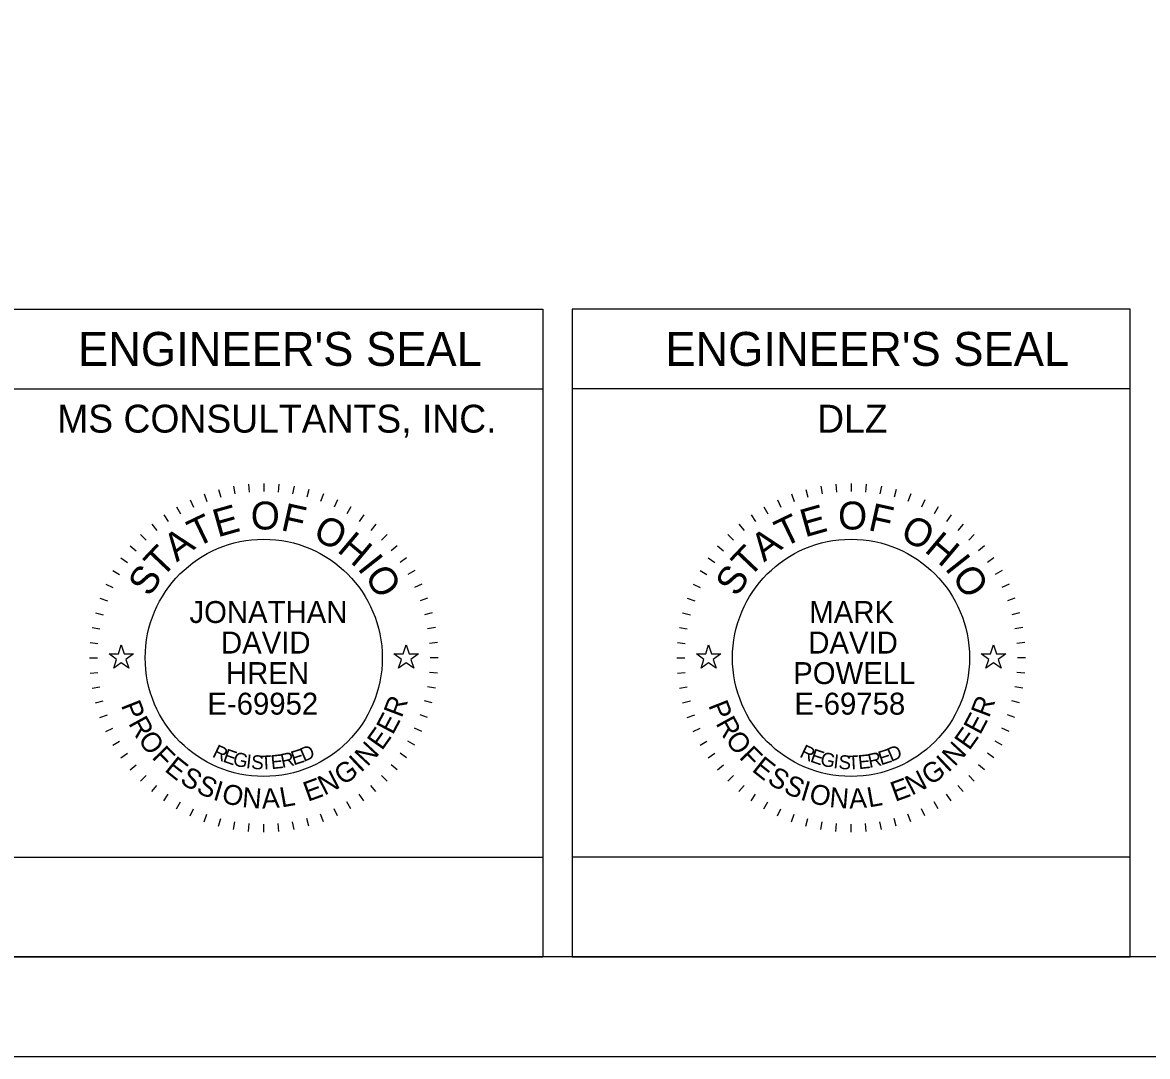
# Model space of a CAD drawing. Extents: x 0 to 34, y -1.2 to 22.
# Drawn here: x 25.22 to 30.87, y 0 to 5.19 of the extents above; entities that cross this region are included whole.
import ezdxf

# ---------------------------------------------------------------- set-up
doc = ezdxf.new("R2010")
doc.units = 0
for name, color, linetype in [('Default', 7, 'Continuous'), ('SH_Border', 7, 'Continuous'), ('SH_Cut_Line', 7, 'Continuous'), ('SH_Data', 7, 'Continuous')]:
    doc.layers.add(name, color=color, linetype=linetype)

msp = doc.modelspace()

# ---------------------------------------------------------------- linework, layer by layer
at = {"layer": 'Default'}
for points in [[(25.6575, 2.02), (25.7044, 2.02), (25.7189, 2.0645), (25.7334, 2.02), (25.7802, 2.02), (25.7423, 1.9924), (25.7568, 1.9478), (25.7189, 1.9754), (25.6809, 1.9478), (25.6954, 1.9924)], [(27.0875, 2.02), (27.1344, 2.02), (27.1489, 2.0645), (27.1634, 2.02), (27.2102, 2.02), (27.1723, 1.9924), (27.1868, 1.9478), (27.1489, 1.9754), (27.1109, 1.9478), (27.1254, 1.9924)], [(28.605, 2.02), (28.6519, 2.02), (28.6664, 2.0645), (28.6809, 2.02), (28.7278, 2.02), (28.6899, 1.9924), (28.7044, 1.9478), (28.6664, 1.9754), (28.6284, 1.9478), (28.6429, 1.9924)], [(30.035, 2.02), (30.0819, 2.02), (30.0964, 2.0645), (30.1109, 2.02), (30.1578, 2.02), (30.1199, 1.9924), (30.1344, 1.9478), (30.0964, 1.9754), (30.0584, 1.9478), (30.0729, 1.9924)]]:
    msp.add_lwpolyline(points, close=True, dxfattribs=at)
at = {"layer": 'SH_Border'}
msp.add_lwpolyline([(1.5, 21.5), (33.5, 21.5), (33.5, 0.5), (1.5, 0.5)], close=True, dxfattribs=at)
at = {"layer": 'SH_Cut_Line'}
msp.add_lwpolyline([(0, 0), (34, 0), (34, 22), (0, 22)], close=True, dxfattribs=at)
at = {"layer": 'SH_Data'}
for p, q in [((25.0339, 3.75), (27.8339, 3.75)), ((27.8339, 3.75), (27.8339, 0.5)), ((30.7814, 3.75), (27.9814, 3.75)), ((27.9814, 3.75), (27.9814, 0.5)), ((30.7814, 0.5), (30.7814, 3.75)), ((25.0339, 3.35), (27.8339, 3.35)), ((30.7814, 3.35), (27.9814, 3.35)), ((26.2074, 2.8452), (26.2178, 2.8065)), ((26.2819, 2.8617), (26.2889, 2.8223)), ((26.3576, 2.8717), (26.3611, 2.8318)), ((26.4339, 2.875), (26.4339, 2.835)), ((26.5101, 2.8717), (26.5066, 2.8318)), ((26.5858, 2.8617), (26.5789, 2.8223)), ((26.6603, 2.8452), (26.65, 2.8065)), ((29.155, 2.8452), (29.1653, 2.8065)), ((29.2295, 2.8617), (29.2364, 2.8223)), ((29.3052, 2.8717), (29.3086, 2.8318)), ((29.3814, 2.875), (29.3814, 2.835)), ((29.4577, 2.8717), (29.4542, 2.8318)), ((29.5334, 2.8617), (29.5264, 2.8223)), ((29.6079, 2.8452), (29.5975, 2.8065)), ((26.0641, 2.793), (26.081, 2.7568)), ((26.1346, 2.8222), (26.1483, 2.7846)), ((26.7331, 2.8222), (26.7195, 2.7846)), ((26.8037, 2.793), (26.7868, 2.7568)), ((29.0116, 2.793), (29.0285, 2.7568)), ((29.0822, 2.8222), (29.0958, 2.7846)), ((29.6807, 2.8222), (29.667, 2.7846)), ((29.7512, 2.793), (29.7343, 2.7568)), ((25.932, 2.7168), (25.9549, 2.684)), ((25.9964, 2.7578), (26.0164, 2.7231)), ((26.8714, 2.7578), (26.8514, 2.7231)), ((26.9357, 2.7168), (26.9128, 2.684)), ((28.8795, 2.7168), (28.9025, 2.684)), ((28.9439, 2.7578), (28.9639, 2.7231)), ((29.8189, 2.7578), (29.7989, 2.7231)), ((29.8833, 2.7168), (29.8604, 2.684)), ((25.8714, 2.6703), (25.8971, 2.6396)), ((26.9963, 2.6703), (26.9706, 2.6396)), ((28.819, 2.6703), (28.8447, 2.6396)), ((29.9439, 2.6703), (29.9181, 2.6396)), ((25.8151, 2.6187), (25.8434, 2.5904)), ((27.0526, 2.6187), (27.0243, 2.5904)), ((28.7627, 2.6187), (28.791, 2.5904)), ((30.0001, 2.6187), (29.9719, 2.5904)), ((25.7636, 2.5624), (25.7942, 2.5367)), ((27.1042, 2.5624), (27.0735, 2.5367)), ((28.7111, 2.5624), (28.7418, 2.5367)), ((30.0517, 2.5624), (30.0211, 2.5367)), ((25.7171, 2.5019), (25.7499, 2.4789)), ((27.1506, 2.5019), (27.1179, 2.4789)), ((28.6647, 2.5019), (28.6974, 2.4789)), ((30.0982, 2.5019), (30.0654, 2.4789)), ((25.6761, 2.4375), (25.7107, 2.4175)), ((27.1916, 2.4375), (27.157, 2.4175)), ((28.6236, 2.4375), (28.6583, 2.4175)), ((30.1392, 2.4375), (30.1045, 2.4175)), ((25.6408, 2.3698), (25.6771, 2.3529)), ((27.2269, 2.3698), (27.1906, 2.3529)), ((28.5884, 2.3698), (28.6247, 2.3529)), ((30.1744, 2.3698), (30.1382, 2.3529)), ((25.6116, 2.2993), (25.6492, 2.2856)), ((27.2561, 2.2993), (27.2185, 2.2856)), ((28.5592, 2.2993), (28.5968, 2.2856)), ((30.2036, 2.2993), (30.1661, 2.2856)), ((25.5887, 2.2265), (25.6273, 2.2161)), ((27.279, 2.2265), (27.2404, 2.2161)), ((28.5362, 2.2265), (28.5749, 2.2161)), ((30.2266, 2.2265), (30.188, 2.2161)), ((25.5722, 2.1519), (25.6115, 2.145)), ((27.2956, 2.1519), (27.2562, 2.145)), ((28.5197, 2.1519), (28.5591, 2.145)), ((30.2431, 2.1519), (30.2037, 2.145)), ((25.5622, 2.0763), (25.602, 2.0728)), ((27.3055, 2.0763), (27.2657, 2.0728)), ((28.5097, 2.0763), (28.5496, 2.0728)), ((30.2531, 2.0763), (30.2132, 2.0728)), ((25.5589, 2), (25.5989, 2)), ((27.3089, 2), (27.2689, 2)), ((28.5064, 2), (28.5464, 2)), ((30.2564, 2), (30.2164, 2)), ((25.5622, 1.9237), (25.602, 1.9272)), ((27.3055, 1.9237), (27.2657, 1.9272)), ((28.5097, 1.9237), (28.5496, 1.9272)), ((30.2531, 1.9237), (30.2132, 1.9272)), ((25.5722, 1.8481), (25.6115, 1.855)), ((27.2956, 1.8481), (27.2562, 1.855)), ((28.5197, 1.8481), (28.5591, 1.855)), ((30.2431, 1.8481), (30.2037, 1.855)), ((25.5887, 1.7735), (25.6273, 1.7839)), ((27.279, 1.7735), (27.2404, 1.7839)), ((28.5362, 1.7735), (28.5749, 1.7839)), ((30.2266, 1.7735), (30.188, 1.7839)), ((25.6116, 1.7007), (25.6492, 1.7144)), ((27.2561, 1.7007), (27.2185, 1.7144)), ((28.5592, 1.7007), (28.5968, 1.7144)), ((30.2036, 1.7007), (30.1661, 1.7144)), ((25.6408, 1.6302), (25.6771, 1.6471)), ((27.2269, 1.6302), (27.1906, 1.6471)), ((28.5884, 1.6302), (28.6247, 1.6471)), ((30.1744, 1.6302), (30.1382, 1.6471)), ((25.6761, 1.5625), (25.7107, 1.5825)), ((27.1916, 1.5625), (27.157, 1.5825)), ((28.6236, 1.5625), (28.6583, 1.5825)), ((30.1392, 1.5625), (30.1045, 1.5825)), ((25.7171, 1.4981), (25.7499, 1.5211)), ((27.1506, 1.4981), (27.1179, 1.5211)), ((28.6647, 1.4981), (28.6974, 1.5211)), ((30.0982, 1.4981), (30.0654, 1.5211)), ((25.7636, 1.4376), (25.7942, 1.4633)), ((27.1042, 1.4376), (27.0735, 1.4633)), ((28.7111, 1.4376), (28.7418, 1.4633)), ((30.0517, 1.4376), (30.0211, 1.4633)), ((25.8151, 1.3813), (25.8434, 1.4096)), ((25.8714, 1.3297), (25.8971, 1.3604)), ((26.9963, 1.3297), (26.9706, 1.3604)), ((27.0526, 1.3813), (27.0243, 1.4096)), ((28.7627, 1.3813), (28.791, 1.4096)), ((28.819, 1.3297), (28.8447, 1.3604)), ((29.9439, 1.3297), (29.9181, 1.3604)), ((30.0001, 1.3813), (29.9719, 1.4096)), ((25.932, 1.2832), (25.9549, 1.316)), ((26.9357, 1.2832), (26.9128, 1.316)), ((28.8795, 1.2832), (28.9025, 1.316)), ((29.8833, 1.2832), (29.8604, 1.316)), ((25.9964, 1.2422), (26.0164, 1.2769)), ((26.0641, 1.207), (26.081, 1.2432)), ((26.8037, 1.207), (26.7868, 1.2432)), ((26.8714, 1.2422), (26.8514, 1.2769)), ((28.9439, 1.2422), (28.9639, 1.2769)), ((29.0116, 1.207), (29.0285, 1.2432)), ((29.7512, 1.207), (29.7343, 1.2432)), ((29.8189, 1.2422), (29.7989, 1.2769)), ((26.1346, 1.1778), (26.1483, 1.2154)), ((26.2074, 1.1548), (26.2178, 1.1935)), ((26.6603, 1.1548), (26.65, 1.1935)), ((26.7331, 1.1778), (26.7195, 1.2154)), ((29.0822, 1.1778), (29.0958, 1.2154)), ((29.155, 1.1548), (29.1653, 1.1935)), ((29.6079, 1.1548), (29.5975, 1.1935)), ((29.6807, 1.1778), (29.667, 1.2154)), ((26.2819, 1.1383), (26.2889, 1.1777)), ((26.3576, 1.1283), (26.3611, 1.1682)), ((26.4339, 1.125), (26.4339, 1.165)), ((26.5101, 1.1283), (26.5066, 1.1682)), ((26.5858, 1.1383), (26.5789, 1.1777)), ((29.2295, 1.1383), (29.2364, 1.1777)), ((29.3052, 1.1283), (29.3086, 1.1682)), ((29.3814, 1.125), (29.3814, 1.165)), ((29.4577, 1.1283), (29.4542, 1.1682)), ((29.5334, 1.1383), (29.5264, 1.1777)), ((25.0339, 0.5), (27.8339, 0.5)), ((30.7814, 0.5), (27.9814, 0.5))]:
    msp.add_line(p, q, dxfattribs=at)
for points in [[(25.0339, 0.5), (25.0339, 1), (27.8339, 1), (27.8339, 0.5)], [(30.7814, 0.5), (30.7814, 1), (27.9814, 1), (27.9814, 0.5)]]:
    msp.add_lwpolyline(points, close=True, dxfattribs=at)
for centre in [(26.4339, 2), (29.3814, 2)]:
    msp.add_circle(centre, 0.595, dxfattribs=at)

# ---------------------------------------------------------------- texts
for s, height, p in [("ENGINEER'S SEAL", 0.17, (25.5014, 3.465)), ("ENGINEER'S SEAL", 0.17, (28.449, 3.465)), ('MS CONSULTANTS, INC.', 0.14, (25.3971, 3.13)), ('DLZ', 0.14, (29.2112, 3.13)), ('JONATHAN', 0.11, (26.061, 2.1749)), ('MARK', 0.11, (29.1719, 2.1749)), ('DAVID', 0.11, (26.2192, 2.0216)), ('DAVID', 0.11, (29.1668, 2.0216)), ('HREN', 0.11, (26.2444, 1.8684)), ('POWELL', 0.11, (29.0911, 1.8684)), ('E-69952', 0.11, (26.151, 1.7151)), ('E-69758', 0.11, (29.0971, 1.7151))]:
    msp.add_text(s, height=height, dxfattribs=at).set_placement(p)
for s, height, rotation, p in [('E', 0.14, 15.7571, (26.2023, 2.6038)), ('O', 0.14, 359.7812, (26.3686, 2.6443)), ('F', 0.14, 347.4362, (26.5149, 2.6417)), ('E', 0.14, 15.7571, (29.1498, 2.6038)), ('O', 0.14, 359.7812, (29.3161, 2.6443)), ('F', 0.14, 347.4362, (29.4625, 2.6417)), ('T', 0.14, 25.7167, (26.0955, 2.5518)), ('T', 0.14, 25.7167, (29.0431, 2.5518)), ('O', 0.14, 332.2586, (26.6737, 2.6015)), ('O', 0.14, 332.2586, (29.6212, 2.6015)), ('A', 0.14, 36.4747, (25.9973, 2.4781)), ('H', 0.14, 319.9136, (26.797, 2.5361)), ('A', 0.14, 36.4747, (28.9448, 2.4781)), ('H', 0.14, 319.9136, (29.7446, 2.5361)), ('T', 0.14, 46.4344, (25.9222, 2.3964)), ('T', 0.14, 46.4344, (28.8697, 2.3964)), ('I', 0.14, 308.367, (26.9003, 2.4483)), ('I', 0.14, 308.367, (29.8479, 2.4483)), ('S', 0.14, 57.1924, (25.862, 2.3014)), ('O', 0.14, 303.1491, (26.936, 2.4089)), ('S', 0.14, 57.1924, (28.8095, 2.3014)), ('O', 0.14, 303.1491, (29.8836, 2.4089)), ('P', 0.1, 291.494, (25.7161, 1.7621)), ('R', 0.1, 69.2322, (27.1258, 1.6954)), ('P', 0.1, 291.494, (28.6637, 1.7621)), ('R', 0.1, 69.2322, (30.0734, 1.6954)), ('R', 0.1, 298.7311, (25.7528, 1.6717)), ('E', 0.1, 61.9951, (27.0815, 1.6098)), ('R', 0.1, 298.7311, (28.7004, 1.6717)), ('E', 0.1, 61.9951, (30.0291, 1.6098)), ('E', 0.1, 54.758, (27.0272, 1.5314)), ('E', 0.1, 54.758, (29.9747, 1.5314)), ('O', 0.1, 306.4666, (25.7993, 1.5883)), ('N', 0.1, 47.0224, (26.9541, 1.4508)), ('O', 0.1, 306.4666, (28.7469, 1.5883)), ('N', 0.1, 47.0224, (29.9016, 1.4508)), ('F', 0.1, 314.7068, (25.8682, 1.4983)), ('R', 0.07, 334.487, (26.1714, 1.5051)), ('E', 0.07, 341.04, (26.2245, 1.4801)), ('G', 0.07, 347.4752, (26.2753, 1.4618)), ('R', 0.07, 11.9184, (26.5264, 1.4474)), ('E', 0.07, 17.6836, (26.5837, 1.4602)), ('D', 0.07, 23.3052, (26.6349, 1.477)), ('F', 0.1, 314.7068, (28.8157, 1.4983)), ('R', 0.07, 334.487, (29.1189, 1.5051)), ('E', 0.07, 341.04, (29.1721, 1.4801)), ('G', 0.07, 347.4752, (29.2229, 1.4618)), ('R', 0.07, 11.9184, (29.4739, 1.4474)), ('E', 0.07, 17.6836, (29.5312, 1.4602)), ('D', 0.07, 23.3052, (29.5824, 1.477)), ('E', 0.1, 321.4393, (25.9317, 1.4348)), ('I', 0.07, 353.7858, (26.3429, 1.4468)), ('S', 0.07, 356.8926, (26.3696, 1.4429)), ('T', 0.07, 3.0061, (26.4196, 1.4387)), ('E', 0.07, 6.0117, (26.4728, 1.4412)), ('G', 0.1, 35.0469, (26.8319, 1.357)), ('I', 0.1, 43.287, (26.9207, 1.4214)), ('E', 0.1, 321.4393, (28.8792, 1.4348)), ('I', 0.07, 353.7858, (29.2905, 1.4468)), ('S', 0.07, 356.8926, (29.3172, 1.4429)), ('T', 0.07, 3.0061, (29.3671, 1.4387)), ('E', 0.07, 6.0117, (29.4204, 1.4412)), ('G', 0.1, 35.0469, (29.7795, 1.357)), ('I', 0.1, 43.287, (29.8683, 1.4214)), ('S', 0.1, 328.6764, (26.0082, 1.3752)), ('N', 0.1, 27.3113, (26.7383, 1.3075)), ('S', 0.1, 328.6764, (28.9557, 1.3752)), ('N', 0.1, 27.3113, (29.6859, 1.3075)), ('S', 0.1, 335.9134, (26.0903, 1.3266)), ('I', 0.1, 343.1505, (26.1745, 1.2897)), ('O', 0.1, 346.8859, (26.2177, 1.2751)), ('E', 0.1, 20.0742, (26.6551, 1.277)), ('S', 0.1, 335.9134, (29.0378, 1.3266)), ('I', 0.1, 343.1505, (29.1221, 1.2897)), ('O', 0.1, 346.8859, (29.1653, 1.2751)), ('E', 0.1, 20.0742, (29.6026, 1.277)), ('N', 0.1, 355.1261, (26.3227, 1.2517)), ('A', 0.1, 2.8617, (26.4261, 1.2437)), ('L', 0.1, 10.0987, (26.5233, 1.249)), ('N', 0.1, 355.1261, (29.2702, 1.2517)), ('A', 0.1, 2.8617, (29.3737, 1.2437)), ('L', 0.1, 10.0987, (29.4708, 1.249))]:
    msp.add_text(s, height=height, rotation=rotation, dxfattribs=at).set_placement(p)

doc.saveas('drawing.dxf')
